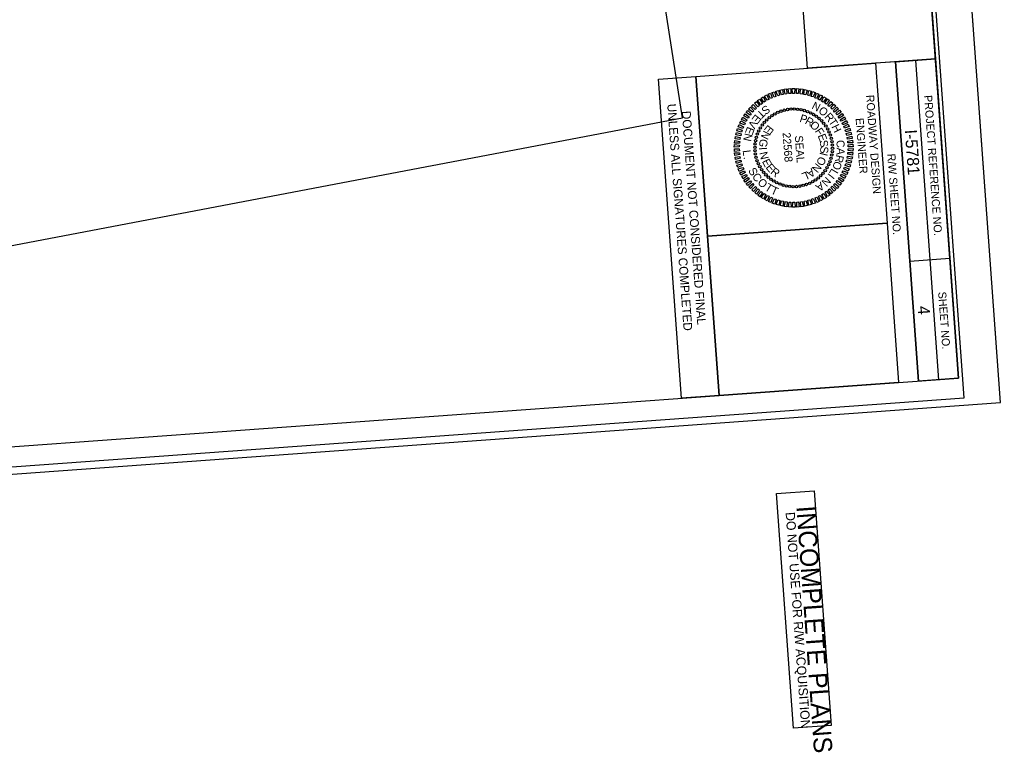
# Model space of a CAD drawing. Extents: x 2130580 to 2131806, y 642587 to 644485.
# Drawn here: x 2131193 to 2131806, y 642587 to 643045 of the extents above; entities that cross this region are included whole.
import ezdxf

# ---------------------------------------------------------------- set-up
doc = ezdxf.new("R2010")
doc.units = 0
for name, color, linetype in [('Old_Level_58', 7, 'Continuous'), ('Scratch_Level_1', 7, 'Continuous'), ('Sheet Border Standard 30in CELL', 7, 'Continuous'), ('Sheet Cutting Line CELL', 7, 'Continuous'), ('Sheet Data Field CELL', 7, 'Continuous'), ('Sheet PE Seal Cell', 7, 'Continuous'), ('Sheet Plot Border Inside CELL', 7, 'Continuous'), ('Sheet Plot Border Outside CELL', 7, 'Continuous'), ('Sheet Sticker Exception Certification CELL', 7, 'Continuous'), ('Sheet Sticker Incomplete CELL', 7, 'Continuous')]:
    doc.layers.add(name, color=color, linetype=linetype)

msp = doc.modelspace()

# ---------------------------------------------------------------- linework, layer by layer
at = {"layer": 'Old_Level_58'}
msp.add_lwpolyline([(2131747.69, 643259.81), (2131765.03, 643020.38), (2131685.21, 643014.6), (2131667.87, 643254.03)], close=True, dxfattribs=at)
at = {"layer": 'Scratch_Level_1'}
msp.add_lwpolyline([(2131551.07, 644337.91), (2130579.8, 644180.68), (2130824.52, 642834.57), (2131607.08, 642983.58), (2131586.04, 643119.01), (2131781.17, 643164.17)], close=True, dxfattribs=at)
at = {"layer": 'Sheet Border Standard 30in CELL'}
for p, q in [((2131740.05, 643018.57), (2131727.58, 643017.67)), ((2131740.05, 643018.57), (2131754.5, 642819.04)), ((2131740.05, 643018.57), (2131754.5, 642819.04)), ((2131752.52, 643019.47), (2131766.97, 642819.94)), ((2131734.81, 642917.88), (2131622.65, 642909.75)), ((2131774.02, 642895.65), (2131749.08, 642893.85))]:
    msp.add_line(p, q, dxfattribs=at)
for points in [[(2131779.49, 642820.85), (2131671.12, 644316.93), (2130623.86, 644241.07), (2130732.23, 642744.99)], [(2131727.58, 643017.67), (2131734.81, 642917.88), (2131622.6, 642909.75), (2131615.38, 643009.54)], [(2131765.03, 643020.38), (2131779.49, 642820.85), (2131754.5, 642819.04), (2131740.05, 643018.57)], [(2131734.81, 642917.88), (2131742.03, 642818.14), (2131629.83, 642810.01), (2131622.6, 642909.75)]]:
    msp.add_lwpolyline(points, close=True, dxfattribs=at)
at = {"layer": 'Sheet Cutting Line CELL'}
msp.add_line((2131805.65, 642805.7), (2131683.99, 644485.3), dxfattribs=at)
at = {"layer": 'Sheet PE Seal Cell'}
for points in [[(2131659.95, 642994.56), (2131658.28, 642997.2), (2131659.72, 642997.93), (2131660.96, 642995.11)], [(2131662.07, 642995.64), (2131660.58, 642998.39), (2131662.06, 642999.02), (2131663.1, 642996.12)], [(2131664.25, 642996.58), (2131662.95, 642999.42), (2131664.48, 642999.94), (2131665.32, 642996.98)], [(2131666.49, 642997.35), (2131665.4, 643000.28), (2131666.96, 643000.7), (2131667.58, 642997.68)], [(2131668.78, 642997.97), (2131667.89, 643000.96), (2131669.48, 643001.27), (2131669.9, 642998.22)], [(2131671.11, 642998.43), (2131670.43, 643001.47), (2131672.04, 643001.67), (2131672.24, 642998.6)], [(2131673.46, 642998.72), (2131673, 643001.81), (2131674.62, 643001.89), (2131674.6, 642998.81)], [(2131675.83, 642998.85), (2131675.59, 643001.96), (2131677.2, 643001.93), (2131676.97, 642998.86)], [(2131678.2, 642998.81), (2131678.18, 643001.93), (2131679.79, 643001.79), (2131679.34, 642998.74)], [(2131680.57, 642998.61), (2131680.76, 643001.72), (2131682.35, 643001.47), (2131681.7, 642998.46)], [(2131682.91, 642998.24), (2131683.32, 643001.34), (2131684.89, 643000.98), (2131684.03, 642998.01)], [(2131685.22, 642997.71), (2131685.85, 643000.77), (2131687.39, 643000.3), (2131686.32, 642997.41)], [(2131687.49, 642997.02), (2131688.33, 643000.03), (2131689.84, 642999.45), (2131688.57, 642996.64)], [(2131689.71, 642996.18), (2131690.75, 642999.12), (2131692.22, 642998.44), (2131690.76, 642995.72)], [(2131691.86, 642995.18), (2131693.11, 642998.04), (2131694.52, 642997.26), (2131692.88, 642994.65)], [(2131652.41, 642988.86), (2131650.07, 642990.92), (2131651.25, 642992.03), (2131653.22, 642989.66)], [(2131654.14, 642990.48), (2131651.95, 642992.7), (2131653.21, 642993.72), (2131655.01, 642991.22)], [(2131655.98, 642991.97), (2131653.95, 642994.35), (2131655.28, 642995.28), (2131656.9, 642992.65)], [(2131657.92, 642993.34), (2131656.07, 642995.85), (2131657.45, 642996.68), (2131658.89, 642993.95)], [(2131693.94, 642994.03), (2131695.38, 642996.8), (2131696.74, 642995.92), (2131694.91, 642993.44)], [(2131695.93, 642992.74), (2131697.56, 642995.4), (2131698.86, 642994.43), (2131696.86, 642992.08)], [(2131697.83, 642991.32), (2131699.64, 642993.86), (2131700.86, 642992.8), (2131698.71, 642990.59)], [(2131699.62, 642989.77), (2131701.61, 642992.17), (2131702.75, 642991.03), (2131700.45, 642988.98)], [(2131647.95, 642983.33), (2131645.23, 642984.86), (2131646.15, 642986.19), (2131648.58, 642984.28)], [(2131649.3, 642985.27), (2131646.7, 642986.99), (2131647.72, 642988.25), (2131650, 642986.18)], [(2131650.79, 642987.12), (2131648.32, 642989.02), (2131649.42, 642990.2), (2131651.55, 642987.97)], [(2131701.3, 642988.09), (2131703.45, 642990.35), (2131704.51, 642989.14), (2131702.08, 642987.25)], [(2131702.86, 642986.3), (2131705.16, 642988.41), (2131706.14, 642987.12), (2131703.57, 642985.41)], [(2131704.29, 642984.41), (2131706.74, 642986.35), (2131707.62, 642985), (2131704.94, 642983.47)], [(2131644.73, 642976.99), (2131641.75, 642977.93), (2131642.38, 642979.42), (2131645.15, 642978.05)], [(2131645.65, 642979.17), (2131642.75, 642980.32), (2131643.48, 642981.76), (2131646.15, 642980.2)], [(2131646.73, 642981.29), (2131643.91, 642982.63), (2131644.74, 642984.02), (2131647.29, 642982.28)], [(2131705.59, 642982.42), (2131708.16, 642984.19), (2131708.95, 642982.78), (2131706.17, 642981.44)], [(2131706.74, 642980.35), (2131709.43, 642981.93), (2131710.12, 642980.47), (2131707.25, 642979.33)], [(2131707.75, 642978.2), (2131710.54, 642979.59), (2131711.13, 642978.09), (2131708.19, 642977.15)], [(2131643.35, 642972.45), (2131640.27, 642972.97), (2131640.69, 642974.53), (2131643.62, 642973.56)], [(2131643.96, 642974.74), (2131640.93, 642975.47), (2131641.45, 642977), (2131644.31, 642975.83)], [(2131708.6, 642975.99), (2131711.49, 642977.18), (2131711.96, 642975.64), (2131708.97, 642974.91)], [(2131709.3, 642973.72), (2131712.26, 642974.71), (2131712.63, 642973.14), (2131709.59, 642972.62)], [(2131642.5, 642965.4), (2131639.38, 642965.26), (2131639.46, 642966.87), (2131642.53, 642966.54)], [(2131642.62, 642967.77), (2131639.5, 642967.85), (2131639.69, 642969.45), (2131642.73, 642968.9)], [(2131642.9, 642970.12), (2131639.8, 642970.42), (2131640.1, 642972.01), (2131643.09, 642971.25)], [(2131709.84, 642971.41), (2131712.86, 642972.19), (2131713.12, 642970.6), (2131710.05, 642970.29)], [(2131710.22, 642969.07), (2131713.28, 642969.64), (2131713.43, 642968.03), (2131710.35, 642967.93)], [(2131710.43, 642966.7), (2131713.53, 642967.06), (2131713.56, 642965.44), (2131710.48, 642965.56)], [(2131642.55, 642963.02), (2131639.44, 642962.67), (2131639.41, 642964.29), (2131642.5, 642964.17)], [(2131642.76, 642960.66), (2131639.69, 642960.09), (2131639.54, 642961.7), (2131642.63, 642961.8)], [(2131710.35, 642961.96), (2131713.47, 642961.88), (2131713.28, 642960.28), (2131710.24, 642960.83)], [(2131710.47, 642964.33), (2131713.59, 642964.47), (2131713.51, 642962.85), (2131710.44, 642963.19)], [(2131643.13, 642958.32), (2131640.11, 642957.54), (2131639.85, 642959.13), (2131642.92, 642959.44)], [(2131643.67, 642956.01), (2131640.71, 642955.02), (2131640.34, 642956.59), (2131643.38, 642957.11)], [(2131644.37, 642953.74), (2131641.48, 642952.55), (2131641.01, 642954.09), (2131644, 642954.82)], [(2131709.01, 642954.99), (2131712.04, 642954.26), (2131711.52, 642952.73), (2131708.67, 642953.9)], [(2131709.62, 642957.28), (2131712.7, 642956.76), (2131712.28, 642955.2), (2131709.35, 642956.17)], [(2131710.07, 642959.61), (2131713.17, 642959.31), (2131712.87, 642957.72), (2131709.88, 642958.48)], [(2131645.22, 642951.53), (2131642.43, 642950.13), (2131641.85, 642951.64), (2131644.78, 642952.58)], [(2131646.23, 642949.38), (2131643.54, 642947.79), (2131642.85, 642949.26), (2131645.72, 642950.4)], [(2131647.38, 642947.31), (2131644.81, 642945.54), (2131644.02, 642946.95), (2131646.8, 642948.29)], [(2131706.24, 642948.44), (2131709.06, 642947.1), (2131708.23, 642945.71), (2131705.68, 642947.44)], [(2131707.32, 642950.56), (2131710.22, 642949.41), (2131709.49, 642947.97), (2131706.83, 642949.52)], [(2131708.24, 642952.74), (2131711.22, 642951.8), (2131710.59, 642950.31), (2131707.82, 642951.68)], [(2131648.68, 642945.32), (2131646.24, 642943.38), (2131645.35, 642944.73), (2131648.03, 642946.26)], [(2131650.11, 642943.43), (2131647.81, 642941.32), (2131646.83, 642942.61), (2131649.4, 642944.32)], [(2131651.67, 642941.64), (2131649.52, 642939.37), (2131648.46, 642940.59), (2131650.9, 642942.48)], [(2131702.18, 642942.61), (2131704.66, 642940.71), (2131703.56, 642939.53), (2131701.42, 642941.76)], [(2131703.67, 642944.46), (2131706.27, 642942.73), (2131705.26, 642941.48), (2131702.97, 642943.55)], [(2131705.03, 642946.4), (2131707.74, 642944.87), (2131706.82, 642943.54), (2131704.4, 642945.45)], [(2131653.35, 642939.96), (2131651.36, 642937.56), (2131650.22, 642938.7), (2131652.52, 642940.75)], [(2131655.14, 642938.41), (2131653.33, 642935.87), (2131652.11, 642936.93), (2131654.26, 642939.14)], [(2131657.04, 642936.99), (2131655.41, 642934.32), (2131654.12, 642935.29), (2131656.11, 642937.65)], [(2131659.03, 642935.7), (2131657.59, 642932.93), (2131656.23, 642933.81), (2131658.06, 642936.29)], [(2131695.05, 642936.39), (2131696.91, 642933.88), (2131695.52, 642933.05), (2131694.09, 642935.78)], [(2131696.99, 642937.76), (2131699.02, 642935.38), (2131697.7, 642934.45), (2131696.07, 642937.08)], [(2131698.83, 642939.25), (2131701.02, 642937.03), (2131699.77, 642936.01), (2131697.96, 642938.51)], [(2131700.56, 642940.87), (2131702.9, 642938.8), (2131701.72, 642937.7), (2131699.75, 642940.07)], [(2131661.11, 642934.55), (2131659.86, 642931.69), (2131658.45, 642932.47), (2131660.1, 642935.08)], [(2131663.26, 642933.55), (2131662.22, 642930.61), (2131660.75, 642931.29), (2131662.21, 642934.01)], [(2131665.48, 642932.71), (2131664.64, 642929.7), (2131663.13, 642930.27), (2131664.4, 642933.09)], [(2131667.75, 642932.02), (2131667.13, 642928.96), (2131665.58, 642929.43), (2131666.65, 642932.32)], [(2131670.06, 642931.49), (2131669.65, 642928.39), (2131668.08, 642928.75), (2131668.94, 642931.71)], [(2131672.4, 642931.12), (2131672.21, 642928), (2131670.62, 642928.25), (2131671.27, 642931.27)], [(2131674.77, 642930.92), (2131674.8, 642927.8), (2131673.19, 642927.93), (2131673.63, 642930.99)], [(2131677.14, 642930.88), (2131677.39, 642927.77), (2131675.77, 642927.79), (2131676, 642930.87)], [(2131679.51, 642931.01), (2131679.97, 642927.92), (2131678.36, 642927.83), (2131678.37, 642930.92)], [(2131681.86, 642931.3), (2131682.54, 642928.25), (2131680.94, 642928.05), (2131680.73, 642931.13)], [(2131684.19, 642931.76), (2131685.08, 642928.77), (2131683.49, 642928.45), (2131683.08, 642931.51)], [(2131686.48, 642932.38), (2131687.58, 642929.45), (2131686.02, 642929.03), (2131685.39, 642932.05)], [(2131688.72, 642933.15), (2131690.02, 642930.31), (2131688.49, 642929.78), (2131687.65, 642932.75)], [(2131690.91, 642934.08), (2131692.4, 642931.34), (2131690.91, 642930.71), (2131689.87, 642933.61)], [(2131693.02, 642935.17), (2131694.7, 642932.53), (2131693.26, 642931.8), (2131692.02, 642934.62)]]:
    msp.add_lwpolyline(points, close=True, dxfattribs=at)
for centre in [(2131662.88, 642984.93), (2131664.68, 642986.04), (2131666.57, 642986.99), (2131668.53, 642987.77), (2131670.56, 642988.38), (2131672.63, 642988.81), (2131674.73, 642989.05), (2131676.85, 642989.11), (2131678.96, 642988.99), (2131681.05, 642988.68), (2131683.11, 642988.19), (2131685.12, 642987.53), (2131687.06, 642986.69), (2131688.92, 642985.68), (2131690.69, 642984.52), (2131656.83, 642979.07), (2131658.14, 642980.73), (2131659.6, 642982.27), (2131661.18, 642983.67), (2131692.35, 642983.21), (2131693.89, 642981.75), (2131695.29, 642980.17), (2131696.56, 642978.47), (2131653.83, 642973.5), (2131654.66, 642975.44), (2131655.67, 642977.3), (2131697.67, 642976.67), (2131698.61, 642974.78), (2131699.4, 642972.82), (2131652.36, 642967.34), (2131652.67, 642969.43), (2131653.16, 642971.49), (2131700, 642970.79), (2131700.43, 642968.72), (2131700.67, 642966.62), (2131652.24, 642965.23), (2131652.3, 642963.11), (2131652.54, 642961.01), (2131700.3, 642960.3), (2131700.61, 642962.39), (2131700.73, 642964.5), (2131652.97, 642958.94), (2131653.58, 642956.91), (2131654.36, 642954.95), (2131698.31, 642954.29), (2131699.15, 642956.23), (2131699.81, 642958.24), (2131655.31, 642953.05), (2131656.42, 642951.25), (2131657.68, 642949.56), (2131659.08, 642947.98), (2131693.37, 642947.46), (2131694.83, 642949), (2131696.14, 642950.66), (2131697.3, 642952.43), (2131660.62, 642946.52), (2131662.28, 642945.21), (2131664.05, 642944.05), (2131665.91, 642943.04), (2131667.85, 642942.2), (2131669.86, 642941.54), (2131682.41, 642941.35), (2131684.44, 642941.96), (2131686.4, 642942.74), (2131688.3, 642943.68), (2131690.1, 642944.79), (2131691.79, 642946.06), (2131671.92, 642941.05), (2131674.01, 642940.74), (2131676.12, 642940.62), (2131678.24, 642940.68), (2131680.34, 642940.92)]:
    msp.add_circle(centre, 0.75, dxfattribs=at)
at = {"layer": 'Sheet Plot Border Inside CELL'}
msp.add_lwpolyline([(2131782.93, 642808.57), (2131662.53, 644470.71), (2130610.19, 644394.49), (2130730.59, 642732.34)], close=True, dxfattribs=at)
at = {"layer": 'Sheet Plot Border Outside CELL'}
msp.add_lwpolyline([(2131805.65, 642805.7), (2131683.99, 644485.3), (2130586.86, 644405.83), (2130708.52, 642726.23)], close=True, dxfattribs=at)
at = {"layer": 'Sheet Sticker Exception Certification CELL'}
for p, q in [((2131591.94, 643007.84), (2131615.38, 643009.54)), ((2131615.38, 643009.54), (2131629.83, 642810.02)), ((2131606.39, 642808.32), (2131591.94, 643007.84)), ((2131629.82, 642810.02), (2131606.38, 642808.32))]:
    msp.add_line(p, q, dxfattribs=at)
at = {"layer": 'Sheet Sticker Incomplete CELL'}
msp.add_lwpolyline([(2131665.8, 642748.86), (2131689.24, 642750.55), (2131699.86, 642603.94), (2131676.43, 642602.24)], close=True, dxfattribs=at)

# ---------------------------------------------------------------- texts
at = {"layer": 'Sheet Border Standard 30in CELL'}
for s, height, p in [('ROADWAY DESIGN', 5.0001, (2131721.7, 642997.79)), ('PROJECT REFERENCE NO.', 5.0001, (2131757.96, 642997.61)), ('ENGINEER', 5, (2131715.18, 642983.33)), ('R/W SHEET NO.', 5.0001, (2131734.99, 642961.05)), ('SHEET NO.', 5, (2131766.76, 642874.77))]:
    msp.add_text(s, height=height, rotation=274.14303, dxfattribs=at).set_placement(p)
at = {"layer": 'Sheet Data Field CELL'}
for s, p in [('I-5781   ', (2131745.89, 642975.99)), ('4  ', (2131753.92, 642865.83))]:
    msp.add_text(s, height=7.5, rotation=274.14303, dxfattribs=at).set_placement(p)
at = {"layer": 'Sheet PE Seal Cell'}
for s, rotation, p in [('S', 216.31437, (2131659.43, 642991.89)), ('N', 332.67755, (2131687.27, 642989.54)), ('E', 232.21693, (2131652.68, 642986.18)), ('T', 224.4277, (2131655.78, 642989.21)), ('P', 342.47741, (2131679.82, 642981.24)), ('O', 322.46712, (2131691.47, 642987.24)), ('R', 311.74195, (2131695.37, 642984.06)), ('V', 240.19681, (2131649.95, 642982.67)), ('E', 231.99365, (2131660.52, 642979.56)), ('R', 330.71516, (2131683.09, 642980.22)), ('O', 318.61571, (2131686.16, 642978.49)), ('T', 303.5333, (2131697.92, 642981.17)), ('H', 295.74407, (2131699.93, 642978.11)), ('N', 256.86195, (2131645.96, 642974.31)), ('E', 248.88207, (2131647.56, 642978.45)), ('N', 243.75589, (2131657.86, 642976)), ('22568', 274.14303, (2131669.54, 642974.27)), ('F', 302.80693, (2131689.51, 642975.34)), ('E', 291.12899, (2131691.36, 642972.49)), ('G', 258.80595, (2131655.61, 642970.78)), ('SEAL', 274.14303, (2131677.19, 642972.41)), ('S', 279.36674, (2131692.6, 642969.3)), ('C', 276.10486, (2131703.02, 642969.46)), ('L', 276.95871, (2131644.57, 642963.24)), ('I', 273.856, (2131654.79, 642965.16)), ('N', 282.61144, (2131655, 642961.85)), ('I', 255.44884, (2131693.02, 642962.38)), ('S', 267.40779, (2131693.17, 642965.86)), ('A', 266.59982, (2131703.42, 642965.02)), ('.', 284.42384, (2131645.05, 642959.11)), ('E', 297.6615, (2131656.52, 642956.37)), ('E', 309.42374, (2131658.67, 642952.48)), ('N', 230.88462, (2131690.49, 642955.73)), ('O', 246.6934, (2131692.45, 642959.89)), ('O', 249.34368, (2131702.25, 642957.02)), ('R', 257.55233, (2131703.11, 642960.78)), ('S', 300.39312, (2131647.85, 642950.68)), ('C', 308.50645, (2131650.14, 642946.78)), ('R', 321.18599, (2131661.57, 642949.11)), ('L', 202.49867, (2131684.46, 642950.17)), ('A', 215.83457, (2131687.64, 642952.41)), ('I', 231.15338, (2131698.51, 642949.37)), ('L', 238.61851, (2131700.34, 642952.36)), ('O', 318.01149, (2131653.48, 642942.68)), ('T', 328.73666, (2131658.01, 642938.79)), ('A', 215.00298, (2131693.34, 642943.85)), ('N', 225.21341, (2131696.79, 642947.17)), ('T', 336.52589, (2131661.72, 642936.53))]:
    msp.add_text(s, height=5, rotation=rotation, dxfattribs=at).set_placement(p)
at = {"layer": 'Sheet Sticker Exception Certification CELL'}
for s, p in [('UNLESS ALL SIGNATURES COMPLETED', (2131597.44, 642992.2)), ('DOCUMENT NOT CONSIDERED FINAL', (2131606.58, 642987.77))]:
    msp.add_text(s, height=5.5, rotation=274.14303, dxfattribs=at).set_placement(p)
at = {"layer": 'Sheet Sticker Incomplete CELL'}
for s, height, p in [('INCOMPLETE PLANS', 11.52, (2131678.12, 642740.77)), ('DO NOT USE FOR R/W ACQUISITION', 5.76, (2131671.42, 642737.03))]:
    msp.add_text(s, height=height, rotation=274.14303, dxfattribs=at).set_placement(p)

doc.saveas('drawing.dxf')
